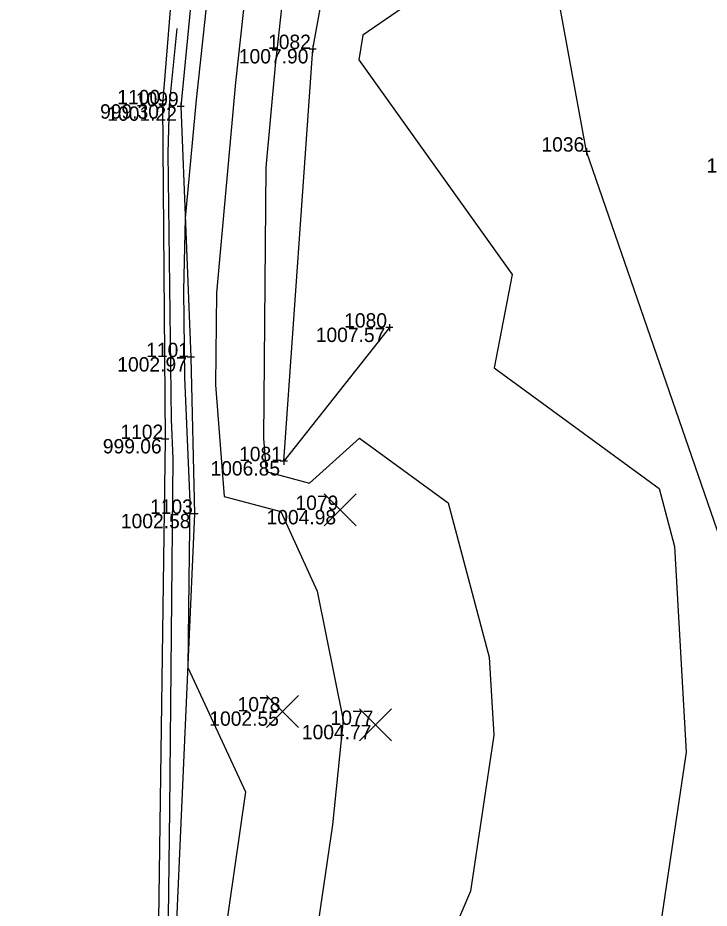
# Model space of a CAD drawing. Extents: x 2354693 to 2355622, y 637071 to 710080.
# Drawn here: x 2355257.5 to 2355315.1, y 709108.7 to 709182.9 of the extents above; entities that cross this region are included whole.
import ezdxf

# ---------------------------------------------------------------- set-up
doc = ezdxf.new("R2010")
doc.units = 0
for name, color, linetype in [('DT_X_Contour_Major', 7, 'Continuous'), ('DT_X_Contour_Minor', 7, 'Continuous'), ('HY_X_Water_Edge', 7, 'Continuous'), ('SV_X_Break_Lines', 7, 'Continuous'), ('SV_X_Random_Point', 7, 'Continuous'), ('SV_X_Shot_Marker', 7, 'Continuous'), ('SV_X_Text_Elevation', 7, 'Continuous'), ('SV_X_Text_Name', 7, 'Continuous'), ('SV_X_Toe_of_Slope', 7, 'Continuous'), ('SV_X_Top_of_Bank', 7, 'Continuous'), ('VG_X_Tree_Line_Rt', 7, 'Continuous')]:
    doc.layers.add(name, color=color, linetype=linetype)

msp = doc.modelspace()

# ---------------------------------------------------------------- linework, layer by layer
at = {"layer": 'DT_X_Contour_Major'}
msp.add_lwpolyline([(2355270.76, 709182.039), (2355270.105, 709175.664), (2355270.004, 709171.687), (2355270.286, 709149.443), (2355270.424, 709146.145), (2355270.143, 709116.895), (2355269.985, 709105.667), (2355272.998, 709093.24), (2355274.998, 709084.414), (2355274.985, 709082.664)], dxfattribs=at)
msp.add_lwpolyline([(2355270.76, 709182.039), (2355270.105, 709175.664), (2355270.004, 709171.687), (2355270.286, 709149.443), (2355270.424, 709146.145), (2355270.143, 709116.895), (2355269.985, 709105.667), (2355272.998, 709093.24), (2355274.998, 709084.414), (2355274.985, 709082.664)], dxfattribs=at)
at = {"layer": 'DT_X_Contour_Minor'}
for points in [[(2355308.937, 709197.105), (2355286.268, 709181.508), (2355285.933, 709179.436), (2355298.723, 709161.538), (2355297.21, 709153.749), (2355310.971, 709143.681), (2355312.263, 709138.834), (2355313.222, 709121.687), (2355310.932, 709106.378), (2355308.326, 709098.925), (2355305.016, 709094.013), (2355300.964, 709090.455), (2355292.296, 709066.739), (2355290.081, 709056.596), (2355281.246, 709038.997), (2355280.856, 709038.326), (2355270.621, 709014.28), (2355257.506, 708990.335)], [(2355308.937, 709197.105), (2355286.268, 709181.508), (2355285.933, 709179.436), (2355298.723, 709161.538), (2355297.21, 709153.749), (2355310.971, 709143.681), (2355312.263, 709138.834), (2355313.222, 709121.687), (2355310.932, 709106.378), (2355308.326, 709098.925), (2355305.016, 709094.013), (2355300.964, 709090.455), (2355292.296, 709066.739), (2355290.081, 709056.596), (2355281.246, 709038.997), (2355280.856, 709038.326), (2355270.621, 709014.28), (2355257.506, 708990.335)], [(2355274.553, 709196.51), (2355272.353, 709176.11), (2355271.449, 709166.241), (2355271.296, 709160.206), (2355271.388, 709152.94), (2355271.823, 709142.596), (2355271.76, 709135.999), (2355271.658, 709128.747), (2355276.476, 709118.372), (2355274.628, 709105.652), (2355276.723, 709085.896), (2355277.177, 709085.206), (2355276.464, 709083.093), (2355275.87, 709080.317), (2355275.376, 709045.66), (2355255.352, 709004.539)], [(2355274.553, 709196.51), (2355272.353, 709176.11), (2355271.449, 709166.241), (2355271.296, 709160.206), (2355271.388, 709152.94), (2355271.823, 709142.596), (2355271.76, 709135.999), (2355271.658, 709128.747), (2355276.476, 709118.372), (2355274.628, 709105.652), (2355276.723, 709085.896), (2355277.177, 709085.206), (2355276.464, 709083.093), (2355275.87, 709080.317), (2355275.376, 709045.66), (2355255.352, 709004.539)], [(2355277.106, 709191.024), (2355275.652, 709177.543), (2355274.046, 709160.009), (2355273.98, 709152.334), (2355274.702, 709143.024), (2355279.419, 709141.755), (2355282.439, 709135.108), (2355284.619, 709124.353), (2355283.723, 709115.633), (2355282.264, 709105.589), (2355283.176, 709096.986), (2355286.896, 709091.337), (2355281.058, 709074.025), (2355276.189, 709051.286), (2355276.108, 709045.628), (2355270.646, 709034.41), (2355255.853, 708999.655)], [(2355277.106, 709191.024), (2355275.652, 709177.543), (2355274.046, 709160.009), (2355273.98, 709152.334), (2355274.702, 709143.024), (2355279.419, 709141.755), (2355282.439, 709135.108), (2355284.619, 709124.353), (2355283.723, 709115.633), (2355282.264, 709105.589), (2355283.176, 709096.986), (2355286.896, 709091.337), (2355281.058, 709074.025), (2355276.189, 709051.286), (2355276.108, 709045.628), (2355270.646, 709034.41), (2355255.853, 708999.655)], [(2355279.659, 709185.538), (2355278.951, 709178.977), (2355278.17, 709170.442), (2355277.974, 709147.861), (2355278.189, 709145.086), (2355281.807, 709144.113), (2355285.994, 709147.892), (2355293.372, 709142.495), (2355296.805, 709129.619), (2355297.17, 709123.096), (2355295.225, 709110.088), (2355292.511, 709103.7), (2355296.614, 709097.469), (2355291.348, 709081.851), (2355286.164, 709067.667), (2355282.419, 709050.516), (2355278.479, 709042.667), (2355278.305, 709042.368), (2355263.237, 709006.968), (2355254.992, 708991.914)], [(2355279.659, 709185.538), (2355278.951, 709178.977), (2355278.17, 709170.442), (2355277.974, 709147.861), (2355278.189, 709145.086), (2355281.807, 709144.113), (2355285.994, 709147.892), (2355293.372, 709142.495), (2355296.805, 709129.619), (2355297.17, 709123.096), (2355295.225, 709110.088), (2355292.511, 709103.7), (2355296.614, 709097.469), (2355291.348, 709081.851), (2355286.164, 709067.667), (2355282.419, 709050.516), (2355278.479, 709042.667), (2355278.305, 709042.368), (2355263.237, 709006.968), (2355254.992, 708991.914)]]:
    msp.add_lwpolyline(points, dxfattribs=at)
at = {"layer": 'HY_X_Water_Edge'}
msp.add_lwpolyline([(2355272.745, 709215.096), (2355272.744, 709215.094), (2355269.55, 709175.728), (2355269.77, 709147.806), (2355269.191, 709105.646), (2355274.675, 709084.438), (2355274.446, 709045.701), (2355249.642, 708995.534), (2355233.297, 708975.074), (2355214.476, 708950.609), (2355202.846, 708934.667), (2355185.207, 708913.176), (2355155.78, 708878.518), (2355144.347, 708868.897), (2355107.99, 708834.305)], dxfattribs=at)
at = {"layer": 'SV_X_Break_Lines'}
msp.add_lwpolyline([(2355288.471, 709157.099), (2355279.67, 709145.962), (2355282.08, 709180.336), (2355287.343, 709209.312), (2355300.192, 709238.194), (2355314.341, 709248.333), (2355340.498, 709257.583), (2355343.401, 709262.657)], dxfattribs=at)
at = {"layer": 'SV_X_Random_Point'}
for p, q in [((2355283.045, 709140.553), (2355285.712, 709143.223)), ((2355283.045, 709143.223), (2355285.712, 709140.553)), ((2355278.238, 709123.752), (2355280.905, 709126.422)), ((2355278.238, 709126.422), (2355280.905, 709123.752)), ((2355285.982, 709122.626), (2355288.648, 709125.296)), ((2355285.982, 709125.296), (2355288.648, 709122.626))]:
    msp.add_line(p, q, dxfattribs=at)
at = {"layer": 'SV_X_Shot_Marker'}
for p, q in [((2355282.08, 709180.636), (2355282.08, 709180.036)), ((2355282.38, 709180.336), (2355281.78, 709180.336)), ((2355269.85, 709175.728), (2355269.25, 709175.728)), ((2355269.55, 709176.028), (2355269.55, 709175.428)), ((2355271.369, 709175.552), (2355270.769, 709175.552)), ((2355271.069, 709175.852), (2355271.069, 709175.252)), ((2355305.211, 709171.779), (2355304.611, 709171.779)), ((2355304.911, 709172.079), (2355304.911, 709171.479)), ((2355288.771, 709157.099), (2355288.171, 709157.099)), ((2355288.471, 709157.399), (2355288.471, 709156.799)), ((2355272.223, 709154.637), (2355271.623, 709154.637)), ((2355271.923, 709154.937), (2355271.923, 709154.337)), ((2355269.77, 709148.106), (2355269.77, 709147.506)), ((2355270.07, 709147.806), (2355269.47, 709147.806)), ((2355279.97, 709145.962), (2355279.37, 709145.962)), ((2355279.67, 709146.262), (2355279.67, 709145.662)), ((2355272.53, 709141.563), (2355271.93, 709141.563)), ((2355272.23, 709141.863), (2355272.23, 709141.263))]:
    msp.add_line(p, q, dxfattribs=at)
at = {"layer": 'SV_X_Toe_of_Slope'}
msp.add_lwpolyline([(2355342.789, 709267.265), (2355319.664, 709264.933), (2355304.718, 709256.214), (2355286.482, 709242.448), (2355272.744, 709215.094), (2355269.55, 709175.728), (2355269.77, 709147.806), (2355269.191, 709105.646), (2355274.675, 709084.438), (2355274.446, 709045.701), (2355249.642, 708995.534), (2355233.297, 708975.074), (2355214.476, 708950.609), (2355202.846, 708934.667), (2355185.207, 708913.176), (2355155.78, 708878.518), (2355144.347, 708868.897), (2355107.99, 708834.305)], dxfattribs=at)
at = {"layer": 'SV_X_Top_of_Bank'}
msp.add_lwpolyline([(2355273.361, 709199.07), (2355271.069, 709175.552), (2355271.923, 709154.637), (2355272.23, 709141.563), (2355270.627, 709105.685), (2355275.826, 709084.354), (2355276.251, 709045.622), (2355250.735, 708994.587), (2355235.317, 708973.622), (2355222.777, 708949.559), (2355205.083, 708933.159), (2355186.581, 708911.433), (2355156.503, 708876.841), (2355146.53, 708867.015), (2355127.533, 708842.203), (2355110.992, 708831.539)], dxfattribs=at)
at = {"layer": 'VG_X_Tree_Line_Rt'}
msp.add_lwpolyline([(2355286.869, 709031.333), (2355312.435, 709075.826), (2355322.746, 709120.095), (2355304.911, 709171.779), (2355297.855, 709210.364), (2355206.484, 709334.222), (2355207.856, 709373.595), (2355249.36, 709399.774), (2355239.696, 709433.161), (2355219.428, 709459.419), (2355185.293, 709497.163), (2355152.292, 709534.908)], dxfattribs=at)

# ---------------------------------------------------------------- texts
at = {"layer": 'SV_X_Text_Elevation'}
for s, p in [('1007.90', (2355275.921, 709179.136)), ('999.30', (2355264.349, 709174.528)), ('1001.22', (2355264.95, 709174.352)), ('1008.94', (2355314.929, 709170.026)), ('1007.57', (2355282.334, 709155.899)), ('1002.97', (2355265.785, 709153.437)), ('999.06', (2355264.577, 709146.606)), ('1006.85', (2355273.556, 709144.762)), ('1002.58', (2355266.084, 709140.363)), ('1004.98', (2355278.232, 709140.688)), ('1002.55', (2355273.458, 709123.887)), ('1004.77', (2355281.178, 709122.761))]:
    msp.add_text(s, height=1.2, dxfattribs=at).set_placement(p)
at = {"layer": 'SV_X_Text_Name'}
for s, p in [('1082', (2355278.354, 709180.336)), ('1100', (2355265.784, 709175.728)), ('1099', (2355267.334, 709175.552)), ('1036', (2355301.155, 709171.779)), ('1080', (2355284.706, 709157.099)), ('1101', (2355268.194, 709154.637)), ('1102', (2355266.043, 709147.806)), ('1081', (2355275.942, 709145.962)), ('1103', (2355268.514, 709141.563)), ('1079', (2355280.643, 709141.888)), ('1078', (2355275.818, 709125.087)), ('1077', (2355283.571, 709123.961))]:
    msp.add_text(s, height=1.2, dxfattribs=at).set_placement(p)

doc.saveas('drawing.dxf')
